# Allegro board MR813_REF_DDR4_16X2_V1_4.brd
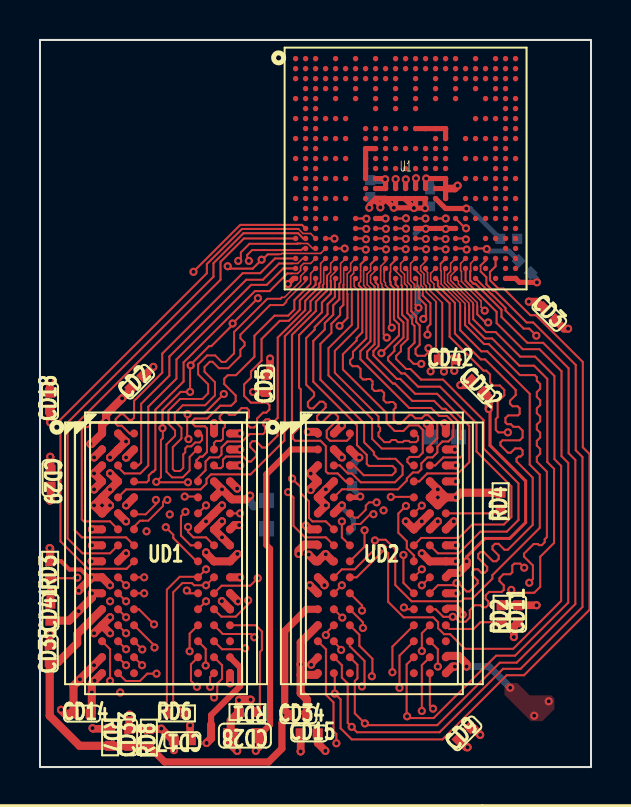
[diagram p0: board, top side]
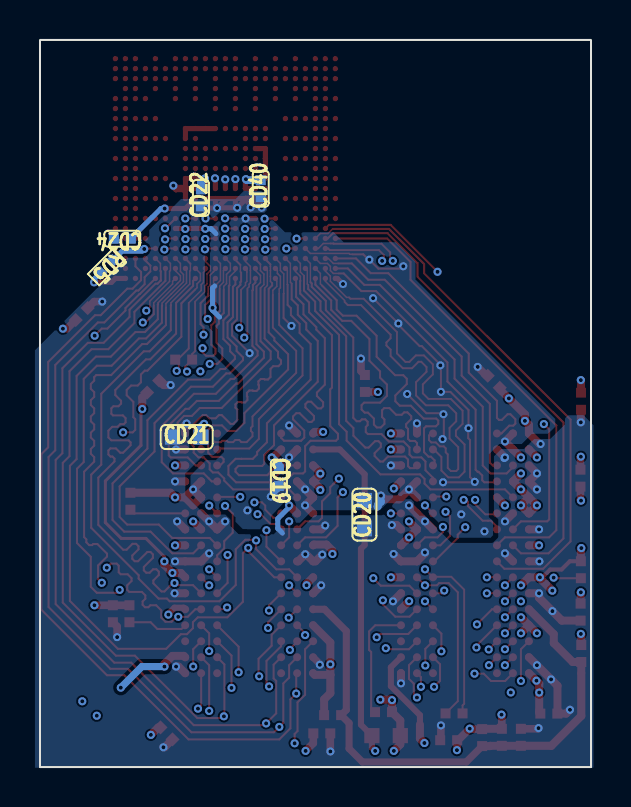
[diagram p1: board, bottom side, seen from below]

Outline 27.56 x 36.39 mm; copper layers: TOP, GND02, POWER03, BOTTOM. Coordinates in mm from the lower left corner of the outline.
Outline path: rectangle 0,0 27.56,36.39

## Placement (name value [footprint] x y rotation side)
CD2  1uF  [C0402]  4.86 19.29 45 top
CD3  1uF  [C0402]  25.47 22.67 315 top
CD5  100nF  [C0402]  11.31 19.2 90 top
CD9  NC/1uF  [C0402]  21.23 1.68 45 top
CD11  100nF  [C0402]  23.91 7.67 90 top
CD12  100nF  [C0402]  21.9 19.04 315 top
CD14  1uF  [C0402]  2.11 2.68 0 top
CD15  1uF  [C0402]  13.46 1.69 0 top
CD17  100nF  [C0402]  7.12 1.34 180 top
CD18  100nF  [C0402]  0.5 18.32 90 top
CD19  1uF  [C0402]  15.61 14.49 270 bottom
CD20  10uF  [C0603]  11.33 12.63 90 bottom
CD21  10uF  [C0603]  20.22 16.52 180 bottom
CD22  1uF  [C0402]  19.51 28.49 90 bottom
CD24  100nF  [C0402]  23.44 26.45 0 bottom
CD28  10uF  [C0603]  10.25 1.57 180 top
CD29  100nF  [C0402]  0.53 14.46 270 top
CD33  100nF  [C0402]  4.46 1.49 90 top
CD34  100nF  [C0402]  12.92 2.6 0 top
CD35  100nF  [C0402]  0.49 5.68 90 top
CD40  NC/1uF  [C0402]  16.52 28.95 90 bottom
CD41  NC/100nF  [C0402]  0.52 7.75 90 top
CD42  NC/2.2nF  [C0402]  20.37 20.39 0 top
NOREF  -  []  -31.22 -1.93 0 top
RD1  240R-1%  [R0402]  10.38 2.75 180 top
RD2  240R-1%  [R0402]  23.09 7.67 90 top
RD3  240R-1%  [R0402]  0.51 9.88 90 top
RD4  240R-1%  [R0402]  23.04 13.3 90 top
RD5  240R-1%  [R0402]  24.24 25.03 315 bottom
RD6  100R  [R0402]  6.85 2.68 0 top
RD7  2K-1%  [R0402]  3.51 1.49 270 top
RD8  2K-1%  [R0402]  5.45 1.47 90 top
U1  MR813  [BGA346P50B1200_1200H114]  18.29 29.96 0 top
UD1  DDR4-FBGA96  [BGA96P80B1000_1400H120]  6.3 10.7 0 top
UD2  DDR4-FBGA96  [BGA96P80B1000_1400H120]  17.1 10.7 0 top

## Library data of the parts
CD2 CD3 CD5 CD9 CD11 CD12 CD14 CD15 CD17-CD22 CD24 CD29 CD33-CD35 CD40-CD42 = C-C0402-X5R
CD28 = C-C0603-X5R
RD1-RD5 RD7 RD8 = R-R0402-1%
RD6 = R-R0402-5%
U1 = A100-BGA
UD1 UD2 = DDR4-FBGA96

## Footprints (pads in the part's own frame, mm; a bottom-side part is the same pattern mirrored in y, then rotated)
BGA96P80B1000_1400H120
  round 0.4 smd: A1(-3.2,6) A2(-2.4,6) A3(-1.6,6) A7(1.6,6) A8(2.4,6) A9(3.2,6) B1(-3.2,5.2) B2(-2.4,5.2) B3(-1.6,5.2) B7(1.6,5.2) B8(2.4,5.2) B9(3.2,5.2) C1(-3.2,4.4) C2(-2.4,4.4) C3(-1.6,4.4) C7(1.6,4.4) C8(2.4,4.4) C9(3.2,4.4) D1(-3.2,3.6) D2(-2.4,3.6) D3(-1.6,3.6) D7(1.6,3.6) D8(2.4,3.6) D9(3.2,3.6) E1(-3.2,2.8) E2(-2.4,2.8) E3(-1.6,2.8) E7(1.6,2.8) E8(2.4,2.8) E9(3.2,2.8) F1(-3.2,2) F2(-2.4,2) F3(-1.6,2) F7(1.6,2) F8(2.4,2) F9(3.2,2) G1(-3.2,1.2) G2(-2.4,1.2) G3(-1.6,1.2) G7(1.6,1.2) G8(2.4,1.2) G9(3.2,1.2) H1(-3.2,0.4) H2(-2.4,0.4) H3(-1.6,0.4) H7(1.6,0.4) H8(2.4,0.4) H9(3.2,0.4) J1(-3.2,-0.4) J2(-2.4,-0.4) J3(-1.6,-0.4) J7(1.6,-0.4) J8(2.4,-0.4) J9(3.2,-0.4) K1(-3.2,-1.2) K2(-2.4,-1.2) K3(-1.6,-1.2) K7(1.6,-1.2) K8(2.4,-1.2) K9(3.2,-1.2) L1(-3.2,-2) L2(-2.4,-2) L3(-1.6,-2) L7(1.6,-2) L8(2.4,-2) L9(3.2,-2) M1(-3.2,-2.8) M2(-2.4,-2.8) M3(-1.6,-2.8) M7(1.6,-2.8) M8(2.4,-2.8) M9(3.2,-2.8) N1(-3.2,-3.6) N2(-2.4,-3.6) N3(-1.6,-3.6) N7(1.6,-3.6) N8(2.4,-3.6) N9(3.2,-3.6) P1(-3.2,-4.4) P2(-2.4,-4.4) P3(-1.6,-4.4) P7(1.6,-4.4) P8(2.4,-4.4) P9(3.2,-4.4) R1(-3.2,-5.2) R2(-2.4,-5.2) R3(-1.6,-5.2) R7(1.6,-5.2) R8(2.4,-5.2) R9(3.2,-5.2) T1(-3.2,-6) T2(-2.4,-6) T3(-1.6,-6) T7(1.6,-6) T8(2.4,-6) T9(3.2,-6)
BGA346P50B1200_1200H114
  round 0.27 smd: A1(-5.5,5.5) A2(-5,5.5) A3(-4.5,5.5) A5(-3.5,5.5) A7(-2.5,5.5) A9(-1.5,5.5) A11(-0.5,5.5) A12(0,5.5) A13(0.5,5.5) A14(1,5.5) A15(1.5,5.5) A16(2,5.5) A17(2.5,5.5) A19(3.5,5.5) A21(4.5,5.5) A22(5,5.5) A23(5.5,5.5) AA1(-5.5,-4.5) AA2(-5,-4.5) AA3(-4.5,-4.5) AA4(-4,-4.5) AA5(-3.5,-4.5) AA6(-3,-4.5) AA7(-2.5,-4.5) AA8(-2,-4.5) AA9(-1.5,-4.5) AA10(-1,-4.5) AA11(-0.5,-4.5) AA12(0,-4.5) AA13(0.5,-4.5) AA14(1,-4.5) AA15(1.5,-4.5) AA16(2,-4.5) AA17(2.5,-4.5) AA18(3,-4.5) AA19(3.5,-4.5) AA20(4,-4.5) AA21(4.5,-4.5) AA22(5,-4.5) AA23(5.5,-4.5) AB1(-5.5,-5) AB2(-5,-5) AB3(-4.5,-5) AB4(-4,-5) AB5(-3.5,-5) AB6(-3,-5) AB7(-2.5,-5) AB8(-2,-5) AB9(-1.5,-5) AB10(-1,-5) AB11(-0.5,-5) AB12(0,-5) AB13(0.5,-5) AB14(1,-5) AB15(1.5,-5) AB16(2,-5) AB17(2.5,-5) AB18(3,-5) AB19(3.5,-5) AB20(4,-5) AB22(5,-5) AB23(5.5,-5) AC1(-5.5,-5.5) AC2(-5,-5.5) AC3(-4.5,-5.5) AC5(-3.5,-5.5) AC7(-2.5,-5.5) AC9(-1.5,-5.5) AC11(-0.5,-5.5) AC13(0.5,-5.5) AC15(1.5,-5.5) AC17(2.5,-5.5) AC19(3.5,-5.5) AC21(4.5,-5.5) AC22(5,-5.5) AC23(5.5,-5.5) B1(-5.5,5) B2(-5,5) B3(-4.5,5) B4(-4,5) B5(-3.5,5) B6(-3,5) B7(-2.5,5) B8(-2,5) B9(-1.5,5) B10(-1,5) B11(-0.5,5) B12(0,5) B13(0.5,5) B14(1,5) B15(1.5,5) B16(2,5) B17(2.5,5) B18(3,5) B19(3.5,5) B20(4,5) B21(4.5,5) B22(5,5) B23(5.5,5) C1(-5.5,4.5) C2(-5,4.5) C3(-4.5,4.5) C4(-4,4.5) C5(-3.5,4.5) C6(-3,4.5) C7(-2.5,4.5) C8(-2,4.5) C9(-1.5,4.5) C10(-1,4.5) C11(-0.5,4.5) C13(0.5,4.5) C15(1.5,4.5) C17(2.5,4.5) C18(3,4.5) C19(3.5,4.5) C20(4,4.5) C21(4.5,4.5) C22(5,4.5) C23(5.5,4.5) D2(-5,4) D3(-4.5,4) D4(-4,4) D5(-3.5,4) D7(-2.5,4) D9(-1.5,4) D11(-0.5,4) D13(0.5,4) D15(1.5,4) D17(2.5,4) D19(3.5,4) D21(4.5,4) D22(5,4) E1(-5.5,3.5) E2(-5,3.5) E3(-4.5,3.5) E5(-3.5,3.5) E7(-2.5,3.5) E9(-1.5,3.5) E11(-0.5,3.5) E13(0.5,3.5) E15(1.5,3.5) E17(2.5,3.5) E20(4,3.5) E21(4.5,3.5) E22(5,3.5) E23(5.5,3.5) F2(-5,3) F3(-4.5,3) F9(-1.5,3) F11(-0.5,3) F13(0.5,3) F22(5,3) F23(5.5,3) G1(-5.5,2.5) G2(-5,2.5) G3(-4.5,2.5) G4(-4,2.5) G5(-3.5,2.5) G6(-3,2.5) G19(3.5,2.5) G20(4,2.5) G21(4.5,2.5) G22(5,2.5) G23(5.5,2.5) H2(-5,2) H3(-4.5,2) H8(-2,2) H9(-1.5,2) H10(-1,2) H11(-0.5,2) H12(0,2) H13(0.5,2) H14(1,2) H15(1.5,2) H16(2,2) H22(5,2) H23(5.5,2) J1(-5.5,1.5) J2(-5,1.5) J3(-4.5,1.5) J4(-4,1.5) J5(-3.5,1.5) J6(-3,1.5) J8(-2,1.5) J9(-1.5,1.5) J10(-1,1.5) J15(1.5,1.5) J16(2,1.5) J18(3,1.5) J19(3.5,1.5) J20(4,1.5) J21(4.5,1.5) J22(5,1.5) J23(5.5,1.5) K2(-5,1) K3(-4.5,1) K8(-2,1) K9(-1.5,1) K10(-1,1) K11(-0.5,1) K12(0,1) K13(0.5,1) K14(1,1) K15(1.5,1) K16(2,1) K21(4.5,1) K22(5,1) L1(-5.5,0.5) L2(-5,0.5) L3(-4.5,0.5) L4(-4,0.5) L5(-3.5,0.5) L6(-3,0.5) L8(-2,0.5) L9(-1.5,0.5) L10(-1,0.5) L14(1,0.5) L15(1.5,0.5) L16(2,0.5) L18(3,0.5) L19(3.5,0.5) L20(4,0.5) L21(4.5,0.5) L22(5,0.5) L23(5.5,0.5) M2(-5,0) M3(-4.5,0) M8(-2,0) M9(-1.5,0) M10(-1,0) M11(-0.5,0) M12(0,0) M13(0.5,0) M14(1,0) M15(1.5,0) M16(2,0) M21(4.5,0) M22(5,0) N1(-5.5,-0.5) N2(-5,-0.5) N3(-4.5,-0.5) N4(-4,-0.5) N5(-3.5,-0.5) N6(-3,-0.5) N8(-2,-0.5) N9(-1.5,-0.5) N15(1.5,-0.5) N16(2,-0.5) N18(3,-0.5) N19(3.5,-0.5) N20(4,-0.5) N21(4.5,-0.5) N22(5,-0.5) N23(5.5,-0.5) P2(-5,-1) P3(-4.5,-1) P8(-2,-1) P9(-1.5,-1) P10(-1,-1) P11(-0.5,-1) P12(0,-1) P13(0.5,-1) P14(1,-1) P15(1.5,-1) P16(2,-1) P21(4.5,-1) P22(5,-1) R1(-5.5,-1.5) R2(-5,-1.5) R3(-4.5,-1.5) R4(-4,-1.5) R5(-3.5,-1.5) R6(-3,-1.5) R8(-2,-1.5) R9(-1.5,-1.5) R10(-1,-1.5) R11(-0.5,-1.5) R12(0,-1.5) R13(0.5,-1.5) R14(1,-1.5) R15(1.5,-1.5) R16(2,-1.5) R18(3,-1.5) R19(3.5,-1.5) R20(4,-1.5) R21(4.5,-1.5) R22(5,-1.5) R23(5.5,-1.5) T2(-5,-2) T3(-4.5,-2) T21(4.5,-2) T22(5,-2) U1(-5.5,-2.5) U2(-5,-2.5) U3(-4.5,-2.5) U4(-4,-2.5) U5(-3.5,-2.5) U7(-2.5,-2.5) U9(-1.5,-2.5) U11(-0.5,-2.5) U13(0.5,-2.5) U15(1.5,-2.5) U17(2.5,-2.5) U18(3,-2.5) U19(3.5,-2.5) U20(4,-2.5) U21(4.5,-2.5) U22(5,-2.5) U23(5.5,-2.5) V2(-5,-3) V3(-4.5,-3) V7(-2.5,-3) V9(-1.5,-3) V11(-0.5,-3) V13(0.5,-3) V15(1.5,-3) V17(2.5,-3) V22(5,-3) V23(5.5,-3) W1(-5.5,-3.5) W2(-5,-3.5) W3(-4.5,-3.5) W4(-4,-3.5) W7(-2.5,-3.5) W9(-1.5,-3.5) W11(-0.5,-3.5) W13(0.5,-3.5) W15(1.5,-3.5) W17(2.5,-3.5) W20(4,-3.5) W21(4.5,-3.5) W22(5,-3.5) W23(5.5,-3.5) Y2(-5,-4) Y3(-4.5,-4) Y4(-4,-4) Y5(-3.5,-4) Y7(-2.5,-4) Y9(-1.5,-4) Y11(-0.5,-4) Y13(0.5,-4) Y15(1.5,-4) Y17(2.5,-4) Y19(3.5,-4) Y22(5,-4) Y23(5.5,-4)
C0402
  rect 0.5x0.5 smd: 1(-0.425,0) 2(0.425,0)
C0603
  rect 0.76x0.76 smd: 1(-0.71,0) 2(0.71,0)
R0402
  rect 0.5x0.5 smd: 1(-0.425,0) 2(0.425,0)

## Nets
GND: CD2.2 CD3.2 CD5.2 CD9.2 CD11.2 CD12.2 CD14.2 CD15.2 CD17.2 CD18.2 CD19.2 CD20.2 CD21.2 CD22.2 CD24.2 CD28.2 CD29.2 CD33.2 CD34.2 CD35.2 CD40.2 CD41.2 RD1.2 RD2.2 RD3.2 RD4.2 RD5.2 RD8.2 U1.A1(GND1) U1.A23(GND2) U1.AA7(GND58) U1.AA11(GND59) U1.AA13(GND60) U1.AA18(GND61) U1.AC1(GND62) U1.AC22(GND63) U1.AC23(GND64) U1.C17(GND3) U1.C19(GND4) U1.H8(GND5) U1.H9(GND6) U1.H10(GND7) U1.H11(GND8) U1.J3(GND9) U1.J8(GND10) U1.J9(GND11) U1.J10(GND12) U1.J15(GND13) U1.J21(GND14) U1.K10(GND15) U1.K11(GND16) U1.K12(GND17) U1.K13(GND18) U1.K14(GND19) U1.K15(GND20) U1.K16(GND21) U1.L9(GND22) U1.L10(GND23) U1.L14(GND24) U1.L15(GND25) U1.L16(GND26) U1.M9(GND27) U1.M10(GND28) U1.M11(GND29) U1.M12(GND30) U1.M13(GND31) U1.M14(GND32) U1.M15(GND33) U1.M16(GND34) U1.N9(GND35) U1.N15(GND36) U1.N16(GND37) U1.N22(GND38) U1.P9(GND39) U1.P10(GND40) U1.P11(GND41) U1.P12(GND42) U1.P13(GND43) U1.P14(GND44) U1.P15(GND45) U1.P16(GND46) U1.R8(GND47) U1.R16(GND48) U1.R21(GND49) U1.U5(GND50) U1.U9(GND51) U1.V2(GND52) U1.V3(GND53) U1.V13(GND54) U1.V15(GND55) U1.V17(GND56) U1.Y4(GND57) UD1.A2(VSSQ1) UD1.A8(VSSQ2) UD1.B2(VSS1) UD1.C9(VSSQ3) UD1.D2(VSSQ4) UD1.D8(VSSQ5) UD1.E1(VSS2) UD1.E3(VSSQ6) UD1.E8(VSSQ7) UD1.E9(VSS3) UD1.F1(VSSQ8) UD1.G8(VSS4) UD1.H1(VSSQ9) UD1.H9(VSSQ10) UD1.K1(VSS5) UD1.K9(VSS6) UD1.M9(VSS7) UD1.N1(VSS8) UD1.T1(VSS9) UD2.A2(VSSQ1) UD2.A8(VSSQ2) UD2.B2(VSS1) UD2.C9(VSSQ3) UD2.D2(VSSQ4) UD2.D8(VSSQ5) UD2.E1(VSS2) UD2.E3(VSSQ6) UD2.E8(VSSQ7) UD2.E9(VSS3) UD2.F1(VSSQ8) UD2.G8(VSS4) UD2.H1(VSSQ9) UD2.H9(VSSQ10) UD2.K1(VSS5) UD2.K9(VSS6) UD2.M9(VSS7) UD2.N1(VSS8) UD2.T1(VSS9)
VCC25-DRAM: CD28.1 CD29.1 UD1.B1(VPP1) UD1.R9(VPP2) UD2.B1(VPP1) UD2.R9(VPP2)
VCC-DRAM: CD2.1 CD3.1 CD5.1 CD9.1 CD11.1 CD12.1 CD14.1 CD15.1 CD17.1 CD18.1 CD19.1 CD20.1 CD21.1 CD22.1 CD40.1 CD41.1 RD7.1 U1.R9(VCC_DRAM1) U1.R10(VCC_DRAM2) U1.R11(VCC_DRAM3) U1.R12(VCC_DRAM4) U1.R13(VCC_DRAM5) U1.R14(VCC_DRAM6) UD1.A1(VDDQ1) UD1.A9(VDDQ2) UD1.B3(VDD1) UD1.B9(VDD2) UD1.C1(VDDQ3) UD1.D1(VDD3) UD1.D9(VDDQ4) UD1.F2(VDDQ5) UD1.F8(VDDQ6) UD1.G1(VDDQ7) UD1.G7(VDD4) UD1.G9(VDDQ8) UD1.J1(VDD5) UD1.J2(VDDQ9) UD1.J8(VDDQ10) UD1.J9(VDD6) UD1.L1(VDD7) UD1.L9(VDD8) UD1.R1(VDD9) UD1.T9(VDD10) UD2.A1(VDDQ1) UD2.A9(VDDQ2) UD2.B3(VDD1) UD2.B9(VDD2) UD2.C1(VDDQ3) UD2.D1(VDD3) UD2.D9(VDDQ4) UD2.F2(VDDQ5) UD2.F8(VDDQ6) UD2.G1(VDDQ7) UD2.G7(VDD4) UD2.G9(VDDQ8) UD2.J1(VDD5) UD2.J2(VDDQ9) UD2.J8(VDDQ10) UD2.J9(VDD6) UD2.L1(VDD7) UD2.L9(VDD8) UD2.R1(VDD9) UD2.T9(VDD10)
VDD18-DRAM: CD24.1 U1.R15(VDD18_DRAM)
VDD-CPU: U1.K8(VDD_CPU1) U1.K9(VDD_CPU2) U1.L8(VDD_CPU3) U1.M8(VDD_CPU4) U1.N8(VDD_CPU5)
VDD-SYS: U1.H13(VDD_SYS1) U1.H14(VDD_SYS2) U1.H15(VDD_SYS3) U1.H16(VDD_SYS4) U1.J16(VDD_SYS5)
SA0: U1.AC19(SA11) UD1.P3(A0) UD2.P3(A0)
SA1: U1.U15(SA3) UD1.P7(A1) UD2.P7(A1)
SA2: U1.AA19(SA9) UD1.R3(A2) UD2.R3(A2)
SA3: U1.Y15(SBA1) UD1.N7(A3) UD2.N7(A3)
SA4: U1.W15(SBA0) UD1.N3(A4) UD2.N3(A4)
SA5: U1.AB16(SA13) UD1.P8(A5) UD2.P8(A5)
SA6: U1.U13(SA4) UD1.P2(A6) UD2.P2(A6)
SA7: U1.W17(SA7) UD1.R8(A7) UD2.R8(A7)
SA8: U1.AA20(SACT) UD1.R2(A8) UD2.R2(A8)
SA9: U1.AB18(SA8) UD1.R7(A9) UD2.R7(A9)
SA10: U1.AB15(SA16) UD1.M3(A10) UD2.M3(A10)
SA11: U1.AA21(SODT0) UD1.T2(A11) UD2.T2(A11)
SA12: U1.AB12(SA15) UD1.M7(A12) UD2.M7(A12)
SA13: U1.Y17(SA12) UD1.T8(A13) UD2.T8(A13)
SACT: U1.AC13(SA14) UD1.L3(ACT) UD2.L3(ACT)
SBA0: U1.W13(SA5) UD1.N2(BA0) UD2.N2(BA0)
SBA1: U1.AA17(SA0) UD1.N8(BA1) UD2.N8(BA1)
SBG0: U1.Y13(SA6) UD1.M2(BG0) UD2.M2(BG0)
SCAS: U1.AC17(SA10) UD1.M8(A15/CAS) UD2.M8(A15/CAS)
SCKE0: U1.AA16(SCKE0) UD1.K2(CKE0) UD2.K2(CKE0)
SCKN: CD42.2 RD6.2 U1.AB14(SCKN) UD1.K8(CK#) UD2.K8(CK#)
SCKP: CD42.1 RD6.1 U1.AA14(SCKP) UD1.K7(CK) UD2.K7(CK)
SCS0: U1.AB13(SA1) UD1.L7(CS0) UD2.L7(CS0)
SDQ0: U1.Y7(SDQ0) UD1.F7(DQ1)
SDQ1: U1.V7(SDQ1) UD1.H8(DQ5)
SDQ2: U1.Y5(SDQ2) UD1.J7(DQ7)
SDQ3: U1.W7(SDQ3) UD1.H7(DQ3)
SDQ4: U1.W1(SDQ4) UD1.H3(DQ2)
SDQ5: U1.W4(SDQ5) UD1.G2(DQ0)
SDQ6: U1.W2(SDQ6) UD1.H2(DQ4)
SDQ7: U1.W3(SDQ7) UD1.J3(DQ6)
SDQ8: U1.AA1(SDQ8) UD1.A3(DQ8)
SDQ9: U1.AB4(SDQ9) UD1.C8(DQ13)
SDQ10: U1.AB1(SDQ10) UD1.C2(DQ12)
SDQ11: U1.AB3(SDQ11) UD1.C7(DQ11)
SDQ12: U1.AC3(SDQ12) UD1.B8(DQ9)
SDQ13: U1.AA4(SDQ13) UD1.D7(DQ15)
SDQ14: U1.AA3(SDQ14) UD1.D3(DQ14)
SDQ15: U1.AA2(SDQ15) UD1.C3(DQ10)
SDQ16: U1.AC9(SDQ16) UD2.D7(DQ15)
SDQ17: U1.AB9(SDQ17) UD2.C8(DQ13)
SDQ18: U1.AA8(SDQ18) UD2.C7(DQ11)
SDQ19: U1.AB8(SDQ19) UD2.B8(DQ9)
SDQ20: U1.AC5(SDQ20) UD2.A3(DQ8)
SDQ21: U1.AB5(SDQ21) UD2.D3(DQ14)
SDQ22: U1.AA6(SDQ22) UD2.C3(DQ10)
SDQ23: U1.AB6(SDQ23) UD2.C2(DQ12)
SDQ24: U1.Y11(SDQ24) UD2.J3(DQ6)
SDQ25: U1.W9(SDQ25) UD2.H2(DQ4)
SDQ26: U1.V9(SDQ26) UD2.H3(DQ2)
SDQ27: U1.Y9(SDQ27) UD2.G2(DQ0)
SDQ28: U1.AC11(SDQ28) UD2.H7(DQ3)
SDQ29: U1.W11(SDQ29) UD2.J7(DQ7)
SDQ30: U1.AB11(SDQ30) UD2.H8(DQ5)
SDQ31: U1.V11(SDQ31) UD2.F7(DQ1)
SDQM0: U1.U7(SDQM0) UD1.E7(DM0)
SDQM1: U1.AA5(SDQM1) UD1.E2(DM1)
SDQM2: U1.AA9(SDQM2) UD2.E2(DM1)
SDQM3: U1.U11(SDQM3) UD2.E7(DM0)
SDQS0N: U1.Y3(SDQS0N) UD1.F3(DQS0#)
SDQS0P: U1.Y2(SDQS0P) UD1.G3(DQS0)
SDQS1N: U1.AC2(SDQS1N) UD1.A7(DQS1#)
SDQS1P: U1.AB2(SDQS1P) UD1.B7(DQS1)
SDQS2N: U1.AC7(SDQS2N) UD2.A7(DQS1#)
SDQS2P: U1.AB7(SDQS2P) UD2.B7(DQS1)
SDQS3N: U1.AA10(SDQS3N) UD2.F3(DQS0#)
SDQS3P: U1.AB10(SDQS3P) UD2.G3(DQS0)
SODT0: U1.AB17(SBG0) UD1.K3(ODT0) UD2.K3(ODT0)
SRAS: U1.AC15(SCS0) UD1.L8(A16/RAS) UD2.L8(A16/RAS)
SRST: U1.U17(SRST) UD1.P1(RESET) UD2.P1(RESET)
STEN1: RD1.1 UD1.N9(TEN)
STEN2: RD2.1 UD2.N9(TEN)
SVREF: CD33.1 CD34.1 CD35.1 RD7.2 RD8.1 UD1.M1(VREFCA) UD2.M1(VREFCA)
SWE: U1.AA12(SA2) UD1.L2(A14/WE) UD2.L2(A14/WE)
N16281101: RD5.1 U1.Y19(SZQ)
N17928021: RD3.1 UD1.F9(ZQ)
N17931224: RD4.1 UD2.F9(ZQ)

Pads without a net: U1 A2 A3 A5 A7 A9 A11 A12 A13 A14 A15 A16 A17 A19 A21 A22 AA15 AA22 AA23 AB19 AB20 AB22 AB23 AC21 B1 B2 B3 B4 B5 B6 B7 B8 B9 B10 B11 B12 B13 B14 B15 B16 B17 B18 B19 B20 B21 B22 B23 C1 C2 C3 C4 C5 C6 C7 C8 C9 C10 C11 C13 C15 C18 C20 C21 C22 C23 D2 D3 D4 D5 D7 D9 D11 D13 D15 D17 D19 D21 D22 E1 E2 E3 E5 E7 E9 E11 E13 E15 E17 E20 E21 E22 E23 F2 F3 F9 F11 F13 F22 F23 G1 G2 G3 G4 G5 G6 G19 G20 G21 G22 G23 H2 H3 H12 H22 H23 J1 J2 J4 J5 J6 J18 J19 J20 J22 J23 K2 K3 K21 K22 L1 L2 L3 L4 L5 L6 L18 L19 L20 L21 L22 L23 M2 M3 M21 M22 N1 N2 N3 N4 N5 N6 N18 N19 N20 N21 N23 P2 P3 P8 P21 P22 R1 R2 R3 R4 R5 R6 R18 R19 R20 R22 R23 T2 T3 T21 T22 U1 U2 U3 U4 U18 U19 U20 U21 U22 U23 V22 V23 W20 W21 W22 W23 Y22 Y23; UD1 P9 T3 T7; UD2 P9 T3 T7

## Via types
v1: diameter 0.406, hole 0.203, TOP to BOTTOM, 273 vias

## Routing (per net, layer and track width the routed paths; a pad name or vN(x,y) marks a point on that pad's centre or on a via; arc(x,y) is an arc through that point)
GND: length 134.8
  TOP w0.076: U1.AA18 21.04,25.21 21.04,24.85 21.08,24.81 21.08,24.31 22.06,23.32 22.06,23.02 v1(22.24,22.84) ; U1.AA13 18.53,25.21 18.53,24.35 18.72,24.17 18.72,24.02 18.77,23.97 18.77,23.14 ; U1.AA7 15.54,25.21 15.54,24.85 15.37,24.68 15.37,23.7 15.38,23.69 ; U1.Y4 14.04,25.71 12.1,25.71 12.06,25.66 11.94,25.66 ; 17.5,24.75 17.54,24.78 17.54,25.14
  TOP w0.102: 11.94,25.66 11.39,25.66 11.12,25.39 v1(11.08,25.39) 10.64,24.95 9.51,24.95 v1(9.39,25.07) ; U1.AA11 17.79,25.39 17.54,25.14 ; U1.V2 13.11,27.14 10.02,27.14 7.68,24.8 v1(7.68,24.79) ; v1(17.08,20.72) 17.08,20.73 17.95,21.6 17.95,22.16 17.7,22.41 17.7,23.97 17.54,24.14 17.54,24.27 17.5,24.31 17.5,24.75 ; 7.4,14.25 5.84,14.25 v1(5.81,14.28) 6.05,14.51 6.05,16.37 6.14,16.46 6.14,16.94 v1(6.13,16.96) 6.13,17.87 7.03,18.78 v1(7.51,18.78) 7.51,20.07 v1(7.54,20.1) 7.54,20.15 8.46,21.07 8.57,21.07 9.63,22.13 v1(9.63,22.2) v1(10.9,23.47) ; 15.38,23.69 15.38,22.48 v1(14.98,22.08) ; v1(7.43,16.41) 7.36,16.48 7.36,17.64 v1(7.38,17.66) 7.43,17.71 8.23,17.71 v1(9.19,18.67) ; 18.77,23.14 v1(18.93,22.98)
  TOP w0.152: v1(21.34,10.3) 21.34,10.52 22.26,11.44 23.49,11.44 24.29,12.24 24.29,14.32 22.51,16.1 22.51,17.86 v1(22.44,17.92)
  TOP w0.203: v1(2.56,9.5) 2.43,9.5 2.04,9.89 1.47,9.89 1.06,10.3 RD3.2
  TOP w0.254: U1.P16 U1.R16 ; U1.P16 U1.P15 ; U1.P16 U1.N16 U1.N15 19.32,29.46 v1(19.31,29.46) 19.29,29.43 U1.P14 ; v1(24.85,24.26) 23.98,24.26 U1.AC23 U1.AC22 ; v1(18.81,29.47) 18.79,29.45 U1.P13 ; U1.P11 17.79,29.43 v1(17.79,29.43) ; U1.V13 19.28,26.96 v1(19.3,26.94) 19.31,26.96 U1.V15 20.27,26.96 v1(20.29,26.93) 20.32,26.96 U1.V17 ; U1.P9 U1.P10 17.29,29.4 v1(17.26,29.42) 17.23,29.46 U1.N9 ; UD2.E3 15.98,13.5 v1(16.02,13.54) ; U1.AC1 12.68,24.46 v1(12.4,24.18) ; U1.U9 v1(17.28,27.46) ; U1.P12 18.29,29.41 v1(18.3,29.42)
  TOP w0.305: v1(21.14,7.63) 21.14,7.67 20.83,7.98 20.38,7.98 UD2.M9
  TOP w0.381: CD15.2 13.89,1.19 v1(14.27,0.81) ; v1(11.51,20.44) 11.51,19.82 CD5.2 ; v1(6.71,0.85) 6.69,0.86 CD17.2 6.64,1.34 v1(6.07,1.92) 6.04,1.9 RD8.2 ; v1(20.89,29.1) 20.74,28.96 U1.P16 ; v1(24.84,8.1) 24.83,8.1 CD11.2 RD2.2 ; CD33.2 4.46,2.61 v1(4.48,2.62) ; v1(26.41,21.94) 26.21,21.94 CD3.2 ; UD1.A2 v1(4.3,16.3) ; v1(0.5,13.33) 0.53,13.36 CD29.2 ; v1(5.67,20.03) 5.23,19.59 CD2.2
  TOP w0.4: v1(14.23,9.1) 14.23,9.17 UD2.K1 ; UD2.G8 v1(19.9,12.3) ; v1(2.7,6.7) UD1.N1 ; UD1.N1 v1(3.5,7.5) ; UD1.N1 v1(3.5,6.7) ; 13.04,4.61 13.04,4.61 13.82,4.61 UD2.T1 ; v1(21.34,10.3) 21.34,10.12 v1(20.94,9.72) 20.52,9.72 UD2.K9 ; v1(0.51,8.75) 0.52,8.74 CD41.2 ; UD2.B2 v1(15.1,15.5) ; CD35.2 0.49,6.64 v1(0.51,6.66) ; v1(2.56,9.5) UD1.K1 v1(3.5,9.1) ; UD2.H1 13.86,11.14 13.23,11.14 12.93,10.84 v1(12.93,10.67) ; v1(19.9,13.9) UD2.E8 19.9,13.1 UD2.E9 ; v1(19.9,13.9) UD2.D8 ; v1(19.9,13.9) UD2.E9 ; CD14.2 2.59,2.73 v1(2.59,3.73) ; CD12.2 22.44,18.5 v1(22.44,17.92) ; UD1.E1 v1(3.5,13.9) UD1.D2 v1(3.5,14.7) ; UD1.E1 v1(3.5,13.1) UD1.F1 v1(2.7,13.1) UD1.E1 ; v1(9.1,13.9) UD1.D8 ; v1(9.1,13.9) UD1.E9 9.6,13.4 10.32,13.4 v1(10.51,13.59) ; v1(9.1,13.9) UD1.E8 ; UD2.A8 19.5,17.03 v1(19.35,17.18) ; v1(10.01,9.5) 10.01,9.5 UD1.K9 ; v1(13.04,5.14) 13.04,6.24 UD2.N1 ; UD1.T1 v1(2.73,4.32) ; UD2.E9 v1(20.8,13.5) ; UD1.H1 v1(2.6,11.1) ; UD1.E3 v1(4.3,13.1) ; v1(10.01,15.1) UD1.C9 ; UD1.M9 v1(9.1,8.3) ; UD2.D2 v1(14.3,13.9) UD2.E1 v1(14.3,13.1) UD2.F1 ; UD2.H9 v1(20.8,11.1) ; UD1.H9 v1(9.1,11.5) UD1.G8 v1(9.1,12.3) ; v1(9.95,3.35) 9.95,3.35 RD1.2 9.54,2.33 CD28.2 9.54,1.13 v1(9.86,0.81) ; CD33.2 5.43,1.91 RD8.2 ; v1(22.01,1.61) 21.64,1.98 CD9.2 ; UD2.C9 v1(20.8,15.1) ; UD2.A2 v1(15.1,17.1) ; UD1.A8 8.7,17.2 v1(8.71,17.2) ; v1(4.3,16.3) UD1.B2 v1(3.5,15.5) ; v1(0.51,19.37) 0.5,19.36 CD18.2 ; CD34.2 13.35,3.39
  TOP w0.406: 13.35,3.39 13.04,3.7 v1(13.04,5.14) ; v1(9.95,3.35) 9.98,3.37 v1(10.54,3.37) ; RD4.2 21.04,13.73 v1(20.8,13.5) ; v1(2.59,3.73) 2.59,4.18 v1(2.73,4.32) ; RD3.2 0.51,10.94 v1(0.48,10.96) ; v1(1.94,8.83) 2.56,9.45 v1(2.56,9.5)
  POWER03 w0.102: v1(11.08,25.39) 10.75,25.72 9.8,25.72 9.53,25.45 9.53,25.21 v1(9.39,25.07)
  BOTTOM w0.254: v1(19.3,26.94) 19,26.94 18.76,26.7 ; RD5.2 24.85,24.42 v1(24.85,24.26) ; 18.82,24.08 18.93,23.97 v1(18.93,22.98) 18.93,22.87 18.58,22.52 ; CD19.2 15.61,13.94 v1(16.02,13.54)
  BOTTOM w0.381: 10.69,13.02 10.66,13.05 10.66,13.12 10.51,13.27 v1(10.51,13.59) ; v1(17.26,29.42) 17.21,29.38 CD40.2 ; v1(19.31,29.46) 19.51,29.26 CD22.2 ; CD21.2 19.51,17.02 v1(19.35,17.18)
  vias: v1(3.5,8.3) v1(4.01,3.73) v1(5.33,11.8) v1(6.49,12.65) v1(7.4,14.25) v1(17.18,12.85) v1(19.54,19.81)
VCC25-DRAM: length 72.1
  TOP w0.305: 8.56,2.13 8.56,2.6 10.01,4.05 10.01,4.99 UD1.R9 ; UD2.B1 12.57,15.9 11.32,14.65 11.32,11.11 11.51,10.93 11.51,2.12 CD28.1 10.96,0.97 v1(10.79,0.81)
  TOP w0.381: v1(0.51,15.53) 0.53,15.51 CD29.1
  TOP w0.4: v1(21.33,5.03) 21.33,5.16 20.93,5.56 20.37,5.56 UD2.R9 ; v1(2.7,15.5) UD1.B1 ; 8.56,1.43 8.56,2.13
  TOP w0.406: v1(8.33,1.2) 8.56,1.43
  POWER03 w0.406: 10.79,0.22 10.79,0.23 v1(10.79,0.81) ; 8.33,0.22 8.33,0.23 v1(8.33,1.2)
  POWER03 w0.508: 1.35,15.5 1.31,15.46 1.31,14.73 ; 1.35,15.5 v1(2.7,15.5) ; 1.35,15.5 0.54,15.5 ; 25.48,3.01 22.69,0.22 3.18,0.22 1.61,1.79 1.61,3.1 1.31,3.4 1.31,14.73 ; 0.54,15.5 1.31,14.73 ; 0.54,15.5 v1(0.51,15.53)
  BOTTOM w0.356: v1(21.33,5.03) 22.46,5.03 v1(23.52,3.97)
  vias: v1(24.72,2.57) v1(25.44,3.29)
VCC-DRAM: length 56.8
  TOP w0.254: U1.R10 17.27,28.47 16.8,28.47 U1.R9 ; U1.R10 17.29,28.4 ; U1.R10 U1.R11 ; U1.R12 U1.R11 ; U1.R12 U1.R13 ; U1.R12 18.29,28.4 18.69,27.99 v1(17.7,27.99) ; U1.R11 17.79,28.08 v1(17.7,27.99) ; U1.R13 18.79,28.06 v1(18.7,27.98) 19.26,27.98 v1(19.26,27.98) 19.26,28.43 U1.R14 U1.R13 ; 17.29,28.4 17.29,28.39 17.02,28.13 17.02,28.09 ; 17.29,28.4 v1(17.7,27.99) ; U1.R9 16.79,28.33 17.02,28.09 ; U1.R9 16.47,28.14 v1(16.47,28) ; 17.02,28.09 v1(17.02,28.01)
  TOP w0.356: v1(13.56,5.12) 13.56,5.16 UD2.R1
  TOP w0.381: v1(24.45,23.3) 24.85,23.3 CD3.1 ; CD5.1 v1(10.66,18.77) ; CD15.1 13.04,0.78 13.03,0.78 v1(13.03,0.78) ; v1(23.7,6.5) 23.7,7.03 CD11.1 ; RD7.1 2.66,1.91 v1(2.63,1.95) ; CD2.1 4.56,18.91 v1(4.11,18.45) ; CD17.1 7.51,1.38 v1(7.51,2.08)
  TOP w0.4: UD2.A9 20.3,17.12 v1(20.22,17.2) ; v1(9.87,10.67) UD1.J9 UD1.J8 8.31,10.69 v1(8.31,10.74) ; UD2.B3 15.9,15.49 v1(15.97,15.49) ; 1.62,2.68 1.24,2.68 v1(1.05,2.87) ; 1.62,2.68 1.68,2.73 1.68,4.07 ; 1.62,2.68 CD14.1 ; v1(9.1,13.1) UD1.F8 v1(8.3,12.3) UD1.G7 ; v1(13.54,13.87) 13.54,13.94 UD2.D1 13.54,14.65 v1(13.54,14.69) 13.54,14.74 UD2.C1 ; v1(20.75,5.03) 20.63,5.03 UD2.T9 ; v1(21.38,0.99) 21.32,0.99 CD9.1 ; CD18.1 0.51,17.88 v1(0.51,17.25) ; UD2.B9 20.75,15.9 v1(20.75,15.9) ; UD2.J2 14.65,10.3 v1(14.29,10.65) 14.25,10.65 UD2.J1 13.78,10.3 v1(13.44,10.63) ; CD12.1 21.37,19.12 v1(21.03,19.12) ; v1(20.8,10.3) UD2.J9 UD2.J8 v1(19.1,10.7) ; UD1.D9 v1(9.86,13.94) ; v1(20.82,8.7) UD2.L9 ; v1(4.3,15.5) UD1.B3 ; UD1.L9 v1(9.9,8.3) ; v1(4.3,10.7) UD1.J2 ; v1(9.96,12.11) 9.72,12.11 UD1.G9 ; UD2.G9 v1(20.7,12.3) ; v1(2.6,8.7) UD1.L1 ; UD2.D9 v1(20.8,14.3) ; 1.47,7.34 1.45,7.33 CD41.1 ; v1(9.5,4.19) UD1.T9 ; UD1.R1 v1(2.7,5.1) ; UD1.J1 v1(2.58,10.3) ; UD1.A9 v1(10.01,16.7) ; v1(18.3,12.3) UD2.G7 v1(19.1,12.3) UD2.F8 ; UD1.G1 v1(2.6,11.9) ; v1(2.7,13.9) UD1.D1 v1(2.7,14.7) UD1.C1 ; v1(13.4,16.78) 13.82,16.78 UD2.A1 ; v1(13.29,12.09) 13.49,11.9 UD2.G1 ; v1(2.52,16.17) 2.58,16.17 UD1.A1 ; v1(10.01,15.9) UD1.B9 ; UD2.F2 v1(15.1,13.1) ; UD1.F2 v1(4.3,12.3) ; UD2.L1 v1(13.5,9.1)
  TOP w0.406: v1(2.6,8.7) 2.6,8.47 v1(1.93,7.8) 1.47,7.34 ; UD1.A1 3.1,17.13 v1(3.3,17.33) 3.3,17.65 4.09,18.44 ; 1.68,4.07 v1(2,4.39) v1(2.7,5.1)
  GND02 w0.254: v1(13.54,14.69) 13.54,14.74 14.73,15.93 15.61,15.93 15.97,15.57 v1(15.97,15.49)
  GND02 w0.305: 15.95,15.49 v1(15.97,15.49)
  BOTTOM w0.254: v1(15.1,13.1) 15.1,13 15.67,12.43 15.67,11.94 15.44,11.71
  BOTTOM w0.381: v1(4.3,15.5) 4.35,15.46 ; v1(15.97,15.49) 15.61,15.14 CD19.1
VDD18-DRAM: length 4.1
  TOP w0.254: U1.R15 20.29,27.96 v1(21.32,27.96)
  BOTTOM w0.254: v1(21.32,27.96) 21.51,27.96 CD24.1
VDD-CPU: length 2
  TOP w0.254: U1.K9 U1.K8 U1.L8 U1.M8 U1.N8
VDD-SYS: length 2
  TOP w0.254: U1.J16 U1.H16 U1.H15 U1.H14 U1.H13
SA0: length 47.1
  TOP w0.102: UD1.P3 v1(5.12,5.89) ; U1.AC19 22.57,23.67 22.59,23.67 23.28,22.97 23.28,22.85 24.19,21.95 24.47,21.95 v1(24.82,21.59) ; UD2.P3 15.5,6.04 16.23,5.31 16.23,4.13 16.13,4.03 v1(16.1,4.03)
  POWER03 w0.102: v1(24.82,21.59) 24.82,21.18 26.36,19.64 26.36,6.67 24.02,4.33 23.37,4.33 22.65,3.61 22.43,3.61 22.07,3.25 19.83,3.25 19.48,3.61 16.53,3.61 v1(16.1,4.03) 14.6,4.03 14.26,3.7 11.72,3.7 11.34,4.08 10.12,4.08 9.47,4.73 6.48,4.73 5.32,5.89 v1(5.12,5.89)
SA1: length 47.9
  TOP w0.102: UD2.P7 17.98,5.58 v1(17.98,3.96) ; v1(8.29,5.08) 8.29,5.91 UD1.P7 ; U1.U15 v1(20.29,27.46)
  POWER03 w0.102: v1(8.29,5.08) 9.62,5.08 10.26,4.44 12.15,4.44 12.54,4.05 14.05,4.05 14.39,4.39 16.25,4.39 16.68,3.96 v1(17.98,3.96) 19.62,3.96 19.98,3.61 21.92,3.61 22.28,3.96 22.5,3.96 23.22,4.68 23.87,4.68 26.01,6.82 26.01,19.49 24.47,21.03 24.47,21.73 23.27,22.93 23.27,23.44 22.74,23.97 22.05,23.97 20.95,25.07 20.95,26.8 v1(20.29,27.46)
SA2: length 50.5
  TOP w0.076: 21.54,24.83 21.54,25.21 U1.AA19
  TOP w0.102: 21.54,24.83 21.52,24.81 21.52,24.36 21.52,24.35 21.52,24.35 21.68,24.19 21.78,24.19 23.08,22.89 23.08,22.53 24.37,21.24 25.16,21.24 26.44,19.96 26.44,15.71 26.78,15.37 26.78,8.16 23.84,5.22 23,5.22 19.87,2.1 16.34,2.1 v1(16.25,2.18) 15.75,2.69 15.75,4.31 15.87,4.44 15.87,5.12 UD2.R3 ; UD1.R3 4.71,5.5 v1(5.1,5.1)
  POWER03 w0.102: v1(16.25,2.18) 15.94,2.18 15.69,2.44 15.51,2.44 14.98,1.9 9.28,1.9 7.16,4.02 5.86,4.02 5.1,4.77 v1(5.1,5.1)
SA3: length 45.9
  TOP w0.102: v1(7.48,5.79) 7.48,6.68 UD1.N7 ; U1.Y15 20.24,25.96 v1(20.29,25.91) ; UD2.N7 17.63,6.02 v1(17.63,4.74)
  POWER03 w0.102: v1(20.29,25.91) 20.29,25.02 20.42,24.89 20.42,24.68 21.84,23.26 22.33,23.26 22.6,22.99 22.6,22.62 23.76,21.46 23.76,20.73 25.3,19.19 25.3,7.11 23.64,5.46 22.99,5.46 22.21,4.67 21.98,4.67 21.63,4.32 20.27,4.32 19.92,4.67 17.7,4.67 v1(17.63,4.74) 16.9,4.74 16.49,5.15 14.1,5.15 13.71,4.76 12.83,4.76 12.45,5.15 10.56,5.15 9.91,5.79 v1(7.48,5.79)
SA4: length 49.3
  TOP w0.102: UD1.N3 5.73,6.07 v1(5.73,5.98) ; U1.W15 20.25,26.46 v1(20.28,26.43) ; v1(16.6,4.54) 16.63,4.57 16.63,5.42 15.97,6.07 15.97,6.62 UD2.N3
  POWER03 w0.102: v1(20.28,26.43) 20.65,26.06 20.65,25.02 20.78,24.89 20.78,24.81 21.97,23.62 22.48,23.62 22.95,23.14 22.95,22.77 24.11,21.61 24.11,20.88 25.65,19.34 25.65,6.97 23.73,5.04 23.08,5.04 22.36,4.32 22.13,4.32 21.77,3.96 20.13,3.96 19.77,4.32 16.82,4.32 v1(16.6,4.54) 16.4,4.74 14.19,4.74 14.07,4.62 13.86,4.41 12.69,4.41 12.3,4.79 10.41,4.79 9.77,5.44 6.87,5.44 6.33,5.98 v1(5.73,5.98)
SA5: length 41.5
  TOP w0.076: U1.AB16 20.23,24.9 20.23,24.23 21.26,23.2 21.26,23
  TOP w0.102: v1(10.26,5.95) 10.21,5.9 9.1,5.9 UD1.P8 ; v1(19.9,5.03) 19.9,5.03 19.9,5.9 UD2.P8 ; 21.26,23 21.26,22.12 22.21,21.17 22.45,21.17 24,19.62 24.75,19.62 24.85,19.52 24.85,19.34 25.02,19.17 25.02,18.93 24.85,18.77 24.85,18.53 25.02,18.36 25.02,18.12 24.85,17.95 24.85,17.71 25.02,17.55 25.02,17.31 24.85,17.14 24.85,16.9 25.02,16.73 25.02,16.5 24.85,16.33 24.85,16.09 25.02,15.92 25.02,15.68 24.85,15.51 24.85,15.29 25.35,14.78 25.35,11.51 25.24,11.39 25.24,11.25 25.1,11.11 24.95,11.11 24.9,11.16 24.69,11.16 24.21,10.68 24.21,10.54 24.65,10.09 24.65,9.41 v1(24.47,9.22)
  POWER03 w0.102: v1(24.47,9.22) 24.47,6.74 23.56,5.83 22.86,5.83 22.06,5.03 21.84,5.03 21.48,4.67 20.42,4.67 20.06,5.03 v1(19.9,5.03) 18.03,5.03 17.93,5.13 17.01,5.13 16.64,5.51 10.7,5.51 v1(10.26,5.95)
SA6: length 45.3
  TOP w0.102: U1.U13 v1(19.28,27.46) ; v1(15.06,5.86) 15.06,5.91 14.7,6.27 UD2.P2 ; v1(4.3,5.9) UD1.P2
  POWER03 w0.102: v1(19.28,27.46) 19.28,27.46 19.92,26.82 19.92,25.04 20.07,24.89 20.07,24.57 21.86,22.78 21.86,22.08 22.97,20.97 22.97,20.29 24.11,19.15 24.11,10.52 23.86,10.27 23.86,9.08 24.11,8.82 24.11,7.4 23.62,6.9 23.43,6.9 21.91,5.39 18.55,5.39 18.45,5.49 17.16,5.49 16.79,5.86 v1(15.06,5.86) 10.85,5.86 10.41,6.3 10.12,6.3 9.96,6.15 7.51,6.15 7.28,6.37 4.78,6.37 v1(4.3,5.9)
SA7: length 49.7
  TOP w0.102: UD2.R8 19.1,5.1 v1(19.1,2.81) ; v1(21.3,26.41) 21.26,26.46 U1.W17 ; v1(8.71,3.48) 8.86,3.64 8.86,4.17 9.1,4.41 9.1,5.1 UD1.R8
  POWER03 w0.102: v1(8.71,3.48) 9.56,2.63 14.7,2.63 15.3,3.23 15.9,3.23 16.23,2.9 19.01,2.9 v1(19.1,2.81) 19.39,2.52 22.34,2.52 22.72,2.9 23.53,2.9 27.08,6.44 27.08,19.96 25.49,21.55 25.49,21.86 25.1,22.25 24.92,22.25 23.95,23.22 23.95,23.91 23.17,24.68 22.32,24.68 21.7,25.31 21.7,26.2 21.49,26.41 v1(21.3,26.41)
SA8: length 51.7
  TOP w0.076: 22.03,25.1 22.03,25.08 22.04,25.08 22.04,24.81
  TOP w0.102: 22.04,24.81 22.33,24.52 22.33,24.17 22.64,23.85 22.74,23.85 24.34,22.25 24.67,22.25 26.79,20.12 26.79,15.85 27.13,15.52 27.13,8.01 24.04,4.92 23.16,4.92 19.98,1.74 15.86,1.74 v1(15.59,2.01) 15.39,2.21 15.39,4.18 15.1,4.47 15.1,5.1 UD2.R2 ; v1(4.3,5.1) UD1.R2 ; 22.03,25.1 22.29,25.35 U1.AA20
  POWER03 w0.102: v1(4.3,5.1) 4.3,4.8 5.44,3.66 7.02,3.66 9.13,1.54 15.12,1.54 v1(15.59,2.01)
SA9: length 46.4
  TOP w0.102: UD1.R7 7.55,5.14 7.55,4.31 v1(7.85,4.02) ; UD2.R7 18.34,5.14 18.34,2.56 v1(18.36,2.54) 18.45,2.45 19.69,2.45 22.81,5.57 23.76,5.57 26.42,8.23 26.42,15.22 26.08,15.56 26.08,19.81 24.98,20.91 24.14,20.91 22.84,22.22 22.84,22.78 21.29,24.33 U1.AB18
  POWER03 w0.102: v1(18.36,2.54) 16.09,2.54 15.75,2.87 15.45,2.87 14.85,2.27 9.41,2.27 7.85,3.83 v1(7.85,4.02)
SA10: length 40.8
  TOP w0.076: 19.79,23.9 19.7,23.99 19.7,24.18 19.54,24.35 19.54,24.71 U1.AB15
  TOP w0.102: UD2.M3 16.15,7.24 v1(16.15,6.96) ; UD1.M3 4.95,7.9 v1(5.7,7.14) ; v1(23.4,16.75) 22.92,16.75 22.8,16.88 22.8,17.42 22.89,17.51 22.89,18.28 23.22,18.61 23.22,18.87 23,19.1 22.67,19.1 22.51,19.26 22.51,19.65 22.32,19.84 22.18,19.84 20.49,21.54 20.49,23.21 19.79,23.9
  POWER03 w0.102: v1(23.4,16.75) 23.4,10.81 23.15,10.56 23.15,9.45 22.79,9.09 22.79,7.77 21.47,6.45 19.56,6.45 19.46,6.55 17.6,6.55 17.2,6.96 v1(16.15,6.96) 12.14,6.96 11.9,7.21 10.01,7.21 9.67,6.86 7.8,6.86 7.52,7.14 v1(5.7,7.14)
SA11: length 50.2
  TOP w0.102: UD2.T2 14.74,4.65 14.74,3.68 v1(14.74,3.68) 15.03,3.39 15.03,1.94 15.59,1.38 20.13,1.38 23.34,4.59 24.21,4.59 27.49,7.87 27.49,15.67 27.15,16 27.15,20.27 24.81,22.62 24.52,22.62 23.19,23.94 22.93,23.94 22.5,24.37 22.5,24.78 22.79,25.06 U1.AA21 ; UD1.T2 4.29,4.31 5,4.31 5.36,4.67 v1(5.83,4.67)
  POWER03 w0.102: v1(14.74,3.68) 14.41,3.34 11.58,3.34 11.19,3.73 9.46,3.73 8.82,4.37 6.15,4.37 6.11,4.4 6.1,4.4 v1(5.83,4.67)
SA12: length 39.6
  TOP w0.076: U1.AB12 18.38,24.86 18.38,24.26 18.57,24.07 18.57,23.95
  TOP w0.102: 18.57,23.95 18.57,22.81 18.82,22.57 18.82,22.28 18.99,22.11 18.99,21.13 18.78,20.93 18.78,20.69 18.88,20.58 19.25,20.58 19.43,20.76 v1(19.43,20.96) ; v1(18.2,7.98) 18.29,7.9 UD2.M7 ; UD1.M7 v1(8.3,8.3)
  POWER03 w0.102: 19.43,20.97 v1(19.43,20.96) 19.69,20.7 20.19,20.7 20.29,20.8 20.29,21.05 20.19,21.15 19.96,21.15 19.86,21.25 19.86,21.45 19.97,21.56 20.44,21.56 21.55,20.46 21.55,19.62 22.29,18.87 22.29,18.66 22.04,18.41 21.72,18.41 21.62,18.31 21.62,17.97 21.77,17.82 22.04,17.82 22.18,17.69 22.18,17.41 22.33,17.25 22.33,11.46 22.23,11.36 21.93,11.36 21.71,11.14 21.71,10.93 22.08,10.56 22.08,9.89 21.68,9.49 21.68,8.17 21.5,7.98 v1(18.2,7.98) 18.18,7.98 17.63,8.54 14.68,8.54 14.52,8.39 12.79,8.39 12.44,8.73 10.29,8.73 10.21,8.65 9.76,8.65 9.53,8.42 9.53,8.23 9.22,7.93 8.67,7.93 v1(8.3,8.3)
SA13: length 46.1
  TOP w0.102: U1.Y17 21.28,25.96 v1(21.34,25.9) ; v1(8.51,4.02) 8.51,4.5 UD1.T8 ; v1(19.66,2.92) 19.5,3.08 UD2.T8
  POWER03 w0.102: v1(21.34,25.9) 21.42,25.82 21.42,25.11 22.2,24.33 23.02,24.33 23.64,23.71 23.64,23.04 24.73,21.95 24.97,21.95 25.18,21.74 25.18,21.33 26.72,19.79 26.72,6.52 23.45,3.25 22.57,3.25 22.22,2.9 19.7,2.9 19.68,2.92 v1(19.66,2.92) 19.49,2.92 19.16,3.25 16.38,3.25 16.05,3.58 15.15,3.58 14.55,2.99 9.7,2.99 8.67,4.02 v1(8.51,4.02)
SACT: length 42.2
  TOP w0.076: U1.AC13 18.88,24.37 18.88,24.08 18.97,23.99 18.97,23.98 18.96,23.97 18.96,23.82 18.95,23.8 18.95,23.51 18.97,23.49 18.97,23.45
  TOP w0.102: v1(16.11,7.83) 16.11,8.09 UD2.L3 ; 18.97,23.45 19.3,23.12 19.3,22.55 v1(19.17,22.43) ; UD1.L3 v1(5.21,8.7)
  POWER03 w0.102: v1(5.21,8.7) 5.98,7.93 7.86,7.93 8.21,7.57 9.37,7.57 9.72,7.92 12.19,7.92 12.44,7.67 14.81,7.67 14.97,7.83 v1(16.11,7.83) 17.33,7.83 17.9,7.27 20.19,7.27 20.29,7.16 21.18,7.16 22.04,8.03 22.04,9.35 22.44,9.75 22.44,10.86 22.69,11.11 22.69,17.05 22.83,17.19 22.83,18.84 21.9,19.76 21.9,20.53 20.57,21.87 20.03,21.87 19.93,21.97 19.93,22.19 20.03,22.3 20.55,22.3 20.65,22.4 20.65,22.59 20.45,22.79 20,22.79 19.9,22.89 19.9,23.37 19.75,23.52 19.46,23.52 19.29,23.34 19.29,22.54 v1(19.17,22.43)
SBA0: length 42.7
  TOP w0.102: v1(14.3,6.61) 14.3,6.7 UD2.N2 ; U1.W13 19.27,26.46 v1(19.3,26.43) ; v1(4.3,6.7) UD1.N2
  POWER03 w0.102: v1(4.3,6.7) 4.37,6.76 7.4,6.76 7.66,6.51 9.81,6.51 10.16,6.85 11.75,6.85 12.02,6.58 14.28,6.58 v1(14.3,6.61) 17.05,6.61 17.46,6.2 19.26,6.2 19.36,6.1 21.62,6.1 23.14,7.62 23.14,8.94 23.51,9.3 23.51,10.42 23.76,10.67 23.76,19 22.62,20.14 22.62,20.83 21.47,21.98 21.47,22.69 19.71,24.44 19.71,24.89 19.67,24.93 19.67,26.06 v1(19.3,26.43)
SBA1: length 40.6
  TOP w0.076: U1.AA17 20.54,25.21 20.54,24.81 20.38,24.66 20.38,24.29 20.99,23.68 20.99,23.68 21.45,23.22 21.45,23.11
  TOP w0.102: 21.45,23.11 21.45,23.1 21.46,23.09 21.46,22.24 22.25,21.45 22.61,21.45 23.97,20.09 24.71,20.09 25.37,19.43 25.37,15.27 25.71,14.93 25.71,11.22 25.02,10.53 25.02,9.02 24.72,8.72 23.72,8.72 v1(23.57,8.87) ; v1(10.72,6.5) 10.56,6.66 9.14,6.66 UD1.N8 ; v1(19.1,5.8) 19.1,6.7 UD2.N8
  POWER03 w0.102: v1(10.72,6.5) 10.99,6.23 16.92,6.23 17.31,5.84 19.06,5.84 v1(19.1,5.8) 19.16,5.74 21.77,5.74 23.23,7.21 23.4,7.21 23.76,7.57 23.76,8.68 v1(23.57,8.87)
SBG0: length 41
  TOP w0.102: v1(19.31,25.92) 19.27,25.96 U1.Y13 ; v1(15.12,7.48) 14.7,7.9 UD2.M2 ; v1(4.3,7.5) UD1.M2
  POWER03 w0.102: v1(19.31,25.92) 19.42,25.81 19.42,24.95 19.39,24.92 19.39,24.32 21.15,22.55 21.15,21.79 22.26,20.68 22.26,19.95 23.25,18.96 23.25,17.1 23.05,16.9 23.05,10.96 22.79,10.71 22.79,9.6 22.39,9.2 22.39,7.88 21.32,6.81 19.74,6.81 19.64,6.91 17.75,6.91 17.2,7.46 15.13,7.46 v1(15.12,7.48) 14.96,7.32 12.29,7.32 12.04,7.56 9.87,7.56 9.52,7.22 7.95,7.22 7.63,7.54 4.34,7.54 v1(4.3,7.5)
SCAS: length 41.2
  TOP w0.076: U1.AC17 20.93,24.32 20.93,24.18 21.87,23.24 21.87,23.1
  TOP w0.102: v1(10.41,8.35) 10.41,8.15 9.79,7.53 9.07,7.53 UD1.M8 ; v1(22.41,22.25) 22.28,22.25 21.87,22.66 21.87,23.1 ; v1(24.22,9.98) 24.01,10.18 23.72,10.18 23.62,10.08 23.62,9.75 23.52,9.65 23.18,9.65 22.98,9.45 22.98,9.31 23.2,9.1 23.2,8.87 23.09,8.77 22.46,8.77 22.29,8.59 22.29,8.42 22.43,8.29 22.43,8.12 22.31,8 22.14,8 22.04,8.1 21.75,8.1 21.5,7.84 21.5,7.48 21.29,7.27 20.98,7.27 20.73,7.52 v1(20.64,7.52) 20.17,7.52 19.79,7.9 UD2.M8
  POWER03 w0.102: v1(10.41,8.35) 12.27,8.35 12.59,8.03 14.66,8.03 14.82,8.19 17.48,8.19 18.04,7.63 20.53,7.63 v1(20.64,7.52) ; v1(24.22,9.98) 24.47,10.23 24.47,11.01 24.92,11.46 24.92,11.61 24.47,12.05 24.47,12.39 24.62,12.54 24.75,12.54 24.9,12.69 24.9,12.9 24.75,13.05 24.62,13.05 24.47,13.2 24.47,13.41 24.62,13.56 24.75,13.56 24.9,13.71 24.9,13.92 24.75,14.06 24.62,14.06 24.47,14.21 24.47,14.42 24.62,14.57 24.75,14.57 24.9,14.72 24.9,14.93 24.75,15.08 24.62,15.08 24.47,15.23 24.47,15.44 24.62,15.59 24.75,15.59 24.9,15.74 24.9,15.95 24.75,16.1 24.62,16.1 24.47,16.25 24.47,16.46 24.62,16.6 24.75,16.6 24.9,16.75 24.9,16.96 24.75,17.11 24.62,17.11 24.47,17.26 24.47,17.47 24.62,17.62 24.75,17.62 24.9,17.77 24.9,17.98 24.75,18.13 24.62,18.13 24.47,18.28 24.47,18.57 24.56,18.67 24.86,18.67 24.93,18.74 24.93,18.95 24.76,19.12 24.57,19.12 24.47,19.22 24.47,19.37 23.34,20.5 23.34,21.33 v1(22.41,22.25)
SCKE0: length 45.7
  TOP w0.076: 20.04,25.19 20.04,24.85 20.07,24.82 20.07,24.18 21.01,23.23 21.01,23.12
  TOP w0.102: v1(4.3,9.1) UD1.K2 ; U1.AA16 20.29,25.44 20.04,25.19 ; UD2.K2 15.1,9.9 15.74,9.9 16.75,10.91 v1(16.75,11.34) 16.78,11.38 17.29,11.38 17.77,10.9 17.77,9.11 18.58,8.3 21.07,8.3 21.21,8.43 21.63,8.43 22.62,9.43 22.62,9.6 25,11.97 25,14.63 24.49,15.14 24.49,18.68 22.37,20.81 22.07,20.81 21.02,21.87 21.02,23.11 21.01,23.12
  POWER03 w0.102: v1(4.3,9.1) 4.3,9.47 5.41,10.57 6.99,10.57 7.08,10.57 8.06,11.54 8.55,11.54 8.87,11.85 9.4,11.85 9.52,11.73 14.86,11.73 15.1,11.5 16.24,11.5 16.39,11.34 v1(16.75,11.34)
SCKN: length 39.2
  TOP w0.076: 20.12,23.23 19.5,23.85 19.5,24.14 19.38,24.26 19.38,24.76 19.29,24.86 U1.AB14
  TOP w0.097: v1(20.72,19.83) 20.62,19.93 20.62,20.21 CD42.2 20.67,20.39 20.12,20.95 20.12,23.23 ; UD1.K8 v1(8.3,9.1) 7.71,9.1 7.6,9.21 7.12,9.21 6.66,8.75 6.66,3.3 RD6.2 ; UD2.K8 v1(19.1,9.1)
  POWER03 w0.097: v1(8.3,9.1) 8.55,9.34 9.18,9.34 9.81,9.96 15.5,9.96 15.67,9.79 18.1,9.79 18.55,9.34 18.86,9.34 v1(19.1,9.1) 19.2,9.2 19.5,9.2 20.44,10.15 20.44,11.24 20.68,11.48 20.83,11.48 21.47,12.12 21.47,16.9 20.52,17.85 20.52,19.61 20.72,19.81 v1(20.72,19.83)
SCKP: length 39.1
  TOP w0.076: 19.8,23.23 19.8,23.3 19.32,23.78 19.32,24.07 19.21,24.18 19.21,24.68 19.04,24.85 19.04,25.06 19.29,25.31 U1.AA14
  TOP w0.097: 19.8,23.23 19.8,20.82 19.95,20.67 CD42.1 20.3,20.04 20.3,19.89 v1(20.21,19.8) ; v1(8.3,9.9) UD1.K7 7.89,9.48 7.77,9.48 7.73,9.52 6.99,9.52 6.34,8.88 6.34,3.17 6.42,3.09 6.42,2.79 6.42,2.69 RD6.1 ; UD2.K7 v1(19.1,9.9)
  POWER03 w0.097: v1(20.21,19.8) 20.21,17.72 21.16,16.76 21.16,12.25 20.7,11.79 20.55,11.79 20.13,11.37 20.13,10.28 19.36,9.52 19.19,9.52 19.1,9.62 v1(19.1,9.9) 18.86,9.66 18.69,9.66 18.23,10.11 15.8,10.11 15.63,10.28 9.68,10.28 9.05,9.66 8.55,9.66 v1(8.3,9.9)
SCS0: length 42
  TOP w0.076: 19.14,23.71 19.14,24.03 19.05,24.12 19.05,24.62 18.88,24.79 18.79,24.89 U1.AB13
  TOP w0.102: UD2.L7 18.18,9.22 v1(18.18,10.62) ; v1(19.38,21.64) 19.38,22.02 19.53,22.17 19.53,23.22 19.14,23.6 19.14,23.71 ; UD1.L7 7.48,8.7 v1(7.34,8.83)
  POWER03 w0.102: v1(7.34,8.83) 7.04,9.14 7.04,9.47 7.85,10.29 8.06,10.29 8.16,10.39 8.46,10.39 8.84,10.78 9.39,10.78 9.63,11.02 14.42,11.02 14.66,10.79 15.86,10.79 16.03,10.61 18.14,10.61 18.16,10.63 ; 18.16,10.63 v1(18.18,10.62) ; 18.16,10.63 18.16,11.73 18.37,11.94 18.9,11.94 19,11.84 19,11.69 18.66,11.36 18.66,11.22 18.83,11.05 19.47,11.05 19.57,11.15 19.57,12 19.45,12.11 19.45,12.55 19.59,12.69 20.3,12.69 20.41,12.8 20.41,15.75 20.31,15.85 20.1,15.85 20.01,15.76 19.54,15.76 19.39,15.9 18.95,15.9 18.78,16.07 18.78,16.69 18.57,16.9 18.36,16.9 18.1,17.15 18.1,17.31 18.4,17.6 19.17,17.6 19.27,17.7 19.27,17.92 19.08,18.11 17.95,18.11 17.82,18.24 17.82,18.5 17.83,18.5 17.94,18.61 19.2,18.61 19.4,18.8 19.4,19.09 19.28,19.21 17.92,19.21 17.82,19.31 17.82,19.44 19.05,20.67 19.05,21.4 19.3,21.64 v1(19.38,21.64)
SDQ0: length 22.1
  TOP w0.102: v1(8.3,13.1) UD1.F7 ; v1(16.29,25.9) 16.24,25.96 U1.Y7
  POWER03 w0.102: v1(8.3,13.1) 8.3,13.6 8.54,13.84 8.54,14.16 8.65,14.26 8.81,14.26 8.91,14.36 8.91,14.74 8.81,14.84 8.57,14.84 8.47,14.94 8.47,15.25 8.57,15.35 8.87,15.35 8.97,15.45 8.97,15.8 8.87,15.9 8.76,15.9 8.66,16 8.66,16.65 9.06,17.05 9.06,17.35 8.66,17.75 8.66,17.92 8.76,18.01 9.07,18.01 9.62,18.56 9.62,19.13 10.33,19.84 11.81,19.84 12.28,20.3 12.28,20.78 12.13,20.93 11.74,20.93 11.63,21.03 11.63,21.33 11.74,21.43 12.12,21.43 12.22,21.53 12.22,21.83 12.47,22.08 12.47,22.29 12.3,22.45 12.3,22.66 12.45,22.81 12.66,22.81 12.83,22.65 13.04,22.65 13.34,22.95 13.34,23.53 13.48,23.67 14.07,23.67 14.33,23.94 14.33,24.57 14.43,24.68 15.07,24.68 v1(16.29,25.9)
SDQ1: length 22.8
  TOP w0.102: v1(16.32,26.93) 16.3,26.96 U1.V7 ; v1(7.41,12.02) 7.41,11.77 7.68,11.5 8.3,11.5 UD1.H8
  POWER03 w0.102: v1(7.41,12.02) 7.41,12.19 7.94,12.73 8.52,12.73 8.75,12.96 8.75,13.33 8.96,13.54 9.25,13.54 9.46,13.75 9.46,14.1 9.33,14.23 9.33,16.89 9.37,16.93 9.37,17.4 9.99,18.02 9.99,18.98 10.46,19.46 11.96,19.46 12.73,20.22 12.73,21.78 16.66,25.71 16.66,26.59 v1(16.32,26.93)
SDQ2: length 22.8
  TOP w0.102: U1.Y5 15.24,25.96 v1(15.24,25.95) ; v1(6.29,12) 6.67,11.63 6.67,11.46 7.83,10.3 UD1.J7
  POWER03 w0.102: v1(15.24,25.95) 14.94,25.65 13.91,25.65 12.97,24.71 11.8,24.71 11.7,24.61 11.7,24.46 11.91,24.26 11.91,24.09 11.46,23.64 11.46,23.38 11.19,23.11 10.67,23.11 10.01,22.45 10.01,21.82 9.28,21.1 9.28,19.9 8.35,18.96 8.22,18.96 7.86,18.61 7.86,16.35 7.76,16.25 7.76,14.11 7.59,13.94 7.59,13.39 7.38,13.18 7.18,13.18 6.88,12.89 6.88,12.11 6.78,12 v1(6.29,12)
SDQ3: length 23.7
  TOP w0.102: v1(7.28,12.78) 7.05,12.55 7.05,11.58 7.54,11.1 UD1.H7 ; v1(16.3,26.42) 16.27,26.46 U1.W7
  POWER03 w0.102: v1(7.28,12.78) 7.45,12.78 7.95,13.28 7.95,13.8 8.11,13.96 8.11,16.1 8.27,16.26 8.27,18.35 9.8,19.88 9.8,20.99 10.07,21.26 10.35,21.26 10.56,21.06 10.56,20.45 10.68,20.33 10.99,20.33 11.13,20.46 11.13,22.32 12.05,23.23 12.44,23.23 12.71,23.5 12.71,23.85 13.03,24.17 13.51,24.17 13.83,24.5 13.83,24.97 14.08,25.22 15.1,25.22 v1(16.3,26.42)
SDQ4: length 24
  TOP w0.102: U1.W1 10.2,26.46 9.03,25.29 9.03,24.39 1.73,17.1 1.73,11.86 2.09,11.5 4.3,11.5 UD1.H3
SDQ5: length 24.5
  TOP w0.102: v1(14.73,26.45) 14.72,26.46 U1.W4 ; v1(2.36,17.17) 2.09,16.9 2.09,12.4 2.19,12.3 3.5,12.3 UD1.G2
  POWER03 w0.102: v1(2.36,17.17) 2.36,17.73 8.91,24.28 8.91,25.23 9.79,26.11 12.41,26.11 12.86,26.57 14.61,26.57 v1(14.73,26.45)
SDQ6: length 25.1
  TOP w0.102: U1.W2 13.17,26.46 12.91,26.72 10.17,26.72 8.68,25.22 8.68,24.54 1.38,17.24 1.38,11.44 2.13,10.7 3.5,10.7 UD1.H2
SDQ7: length 27.7
  TOP w0.076: U1.W3 13.54,26.71 13.15,26.71 12.93,26.93
  TOP w0.102: 12.93,26.93 10.1,26.93 8.35,25.18 8.35,24.71 1.02,17.39 1.02,11.3 2.4,9.92 4.33,9.92 UD1.J3
SDQ8: length 15
  TOP w0.102: U1.AA1 11.75,25.46 11.02,24.72 10.14,24.72 6.11,20.69 6.11,19.74 4.7,18.33 4.7,17.48 4.6,17.37 4.46,17.37 4.18,17.66 4.03,17.66 3.78,17.41 3.78,17.19 3.89,17.09 4.09,17.09 4.48,16.7 UD1.A3
SDQ9: length 14.7
  TOP w0.076: 14.19,24.86 14.19,24.18 14.14,24.13 ; 14.19,24.86 14.19,24.86 ; 14.19,24.86 U1.AB4
  TOP w0.102: 14.14,24.13 14.14,23.93 13.53,23.31 13.53,22.85 12.25,21.56 12.25,17.33 11.88,16.97 11.88,16.59 11.29,15.99 11.12,15.99 10.8,16.31 10.63,16.31 10.51,16.19 10.51,16.02 10.82,15.71 10.82,15.57 10.55,15.29 10.4,15.29 10.15,15.54 9.3,15.54 9.15,15.39 9.15,15.06 9.05,14.96 8.84,14.96 UD1.C8
SDQ10: length 15.6
  TOP w0.102: UD1.C2 3.9,15.01 4.22,14.7 5.02,14.7 5.42,15.09 5.42,18.03 6.83,19.44 6.83,20.4 10.56,24.13 11.34,24.13 12.16,24.96 U1.AB1
SDQ11: length 15.1
  TOP w0.076: 13.45,24.1 13.53,24.18 13.53,24.71 U1.AB3
  TOP w0.102: UD1.C7 7.82,15.18 7.82,15.35 8.01,15.53 8.13,15.53 8.35,15.76 8.35,16.95 8.25,17.06 7.76,17.06 7.64,17.18 7.64,17.34 7.74,17.44 8.37,17.44 9.01,18.09 9.56,18.09 9.79,18.31 9.79,18.6 9.21,19.17 9.21,19.44 9.39,19.61 9.8,19.61 10.72,20.54 10.72,21.59 11.73,22.59 12.41,22.59 12.72,22.9 12.72,23.37 13.45,24.1
SDQ12: length 15.7
  TOP w0.102: UD1.B8 8.7,16.22 8.81,16.32 9.05,16.32 9.15,16.42 9.15,16.92 9.25,17.02 9.25,17.16 8.99,17.42 8.99,17.56 9.18,17.75 9.35,17.75 9.47,17.63 9.75,17.63 10.08,17.96 10.34,17.96 10.45,17.86 10.45,17.52 10.33,17.4 10.33,17.17 10.51,17 10.71,17 10.86,17.14 10.86,17.44 11.16,17.74 11.32,17.74 11.48,17.9 11.48,18.11 11.35,18.24 10.55,18.24 10.21,18.58 10.21,19.15 10.55,19.49 10.55,19.8 11.08,20.33 11.08,21.42 11.99,22.33 12.44,22.33 12.99,22.89 12.99,23.35 13.79,24.14 U1.AC3
SDQ13: length 15.4
  TOP w0.076: U1.AA4 14.03,25.21 14.03,24.27 14.02,24.26
  TOP w0.102: 14.02,24.26 13.97,24.21 13.97,24.04 13.26,23.33 13.26,22.87 11.89,21.5 11.89,17.48 11.72,17.31 11.55,17.31 11.46,17.4 11.29,17.4 11.17,17.28 11.17,17.11 11.26,17.02 11.26,16.77 11.16,16.67 10.48,16.67 10.11,16.29 9.37,16.29 9.08,16 9.08,15.64 8.94,15.5 8.49,15.5 8.28,15.29 8.28,14.86 7.9,14.48 UD1.D7
SDQ14: length 16.3
  TOP w0.076: 12.61,24.71 12.89,24.71 13.03,24.85 13.03,25.06 13.18,25.21 13.53,25.21 U1.AA3
  TOP w0.102: 12.61,24.71 12.37,24.71 11.48,23.82 10.75,23.82 7.18,20.25 7.18,19.3 5.77,17.89 5.77,14.88 5.67,14.78 5.63,14.78 5.44,14.59 5.44,14.35 5.34,14.25 4.75,14.25 UD1.D3
SDQ15: length 15.2
  TOP w0.076: 12.64,25.21 12.89,25.21 13.14,25.46 U1.AA2
  TOP w0.102: 12.64,25.21 11.96,25.21 11.15,24.39 10.31,24.39 6.47,20.55 6.47,19.59 5.06,18.18 5.06,15.24 4.92,15.1 UD1.C3
SDQ16: length 15.3
  TOP w0.102: U1.AC9 16.79,24.25 16.91,24.13 16.91,23.88 16.94,23.85 16.94,21.08 16.67,20.82 16.67,20.6 17.85,19.43 18.02,19.43 18.76,18.68 19.86,18.68 21.47,17.07 21.47,15.26 20.91,14.7 19.37,14.7 19.12,14.45 18.97,14.3 UD2.D7
SDQ17: length 14.3
  TOP w0.076: 16.73,24.05 16.53,24.25 16.53,24.6 16.79,24.86 U1.AB9
  TOP w0.102: UD2.C8 19.77,15.1 20.17,15.5 21.02,15.5 21.12,15.6 21.12,16.35 21.03,16.44 21.03,17.18 20.28,17.93 20.11,17.93 19.71,18.33 18.62,18.33 17.75,19.2 17.65,19.2 16.36,20.49 16.36,20.79 16.73,21.17 16.73,24.05
SDQ18: length 14.5
  TOP w0.076: 16.03,25.16 16.03,25.06 16.03,24.56 16.03,24.31 15.95,24.22
  TOP w0.102: 15.95,24.22 15.95,24.11 16.12,23.93 16.12,21.76 15.84,21.48 15.84,21.35 15.15,20.66 15.15,19.9 17.33,17.71 17.33,17.23 17.74,16.82 18.18,16.82 18.46,17.1 18.93,17.1 19.15,16.88 19.15,15.73 18.94,15.52 18.48,15.52 18.38,15.41 18.38,15.27 18.55,15.1 UD2.C7 ; U1.AA8 16.29,25.41 16.03,25.16
SDQ19: length 14.1
  TOP w0.076: U1.AB8 16.19,24.86 16.19,24.1 16.32,23.96 16.32,23.88
  TOP w0.102: 16.32,23.88 16.32,21.46 15.65,20.78 15.65,20.5 15.5,20.36 15.5,20.19 15.63,20.06 15.89,20.06 16.03,19.93 16.03,19.52 16.15,19.4 16.32,19.4 16.35,19.42 16.52,19.42 16.63,19.3 16.63,19.13 16.61,19.11 16.61,18.94 16.73,18.82 16.9,18.82 16.92,18.85 17.09,18.85 17.21,18.73 17.21,18.56 17.19,18.54 17.19,18.37 17.3,18.25 17.47,18.25 17.5,18.27 17.67,18.27 17.78,18.15 17.78,17.98 17.69,17.89 17.69,17.37 17.89,17.18 18.03,17.18 18.47,17.62 18.61,17.62 18.77,17.46 19.09,17.46 19.25,17.62 19.42,17.62 19.87,17.16 19.87,16.45 19.5,16.08 UD2.B8
SDQ20: length 13.5
  TOP w0.102: U1.AC5 14.75,24.42 14.75,23.53 14.38,23.16 14.38,22.66 13.74,22.02 13.74,21.9 13.31,21.47 13.31,19.14 13.71,18.74 13.71,18.57 13.4,18.26 13.4,18.06 13.5,17.95 13.66,17.95 14,18.29 14.17,18.29 14.28,18.17 14.28,18 13.86,17.57 13.86,17.39 13.98,17.27 14.13,17.27 14.57,17.71 14.74,17.71 14.9,17.55 14.9,17.4 14.34,16.84 14.34,16.49 14.5,16.33 15.35,16.33 15.5,16.48 UD2.A3
SDQ21: length 14
  TOP w0.076: U1.AB5 14.79,24.81 14.54,24.56 14.54,24.34
  TOP w0.102: 14.54,24.34 14.55,24.32 14.55,23.85 14.55,23.84 14.55,23.7 14.1,23.25 14.1,22.76 12.96,21.62 12.96,18.99 13.04,18.91 13.04,17.07 12.66,16.68 12.66,16.43 12.76,16.33 14.03,16.33 14.3,16.06 14.3,14.8 14.4,14.7 14.89,14.7 15.29,14.3 UD2.D3
SDQ22: length 16.3
  TOP w0.076: U1.AA6 15.03,25.21 15.03,24.26 14.97,24.2
  TOP w0.102: 14.97,24.2 14.97,23.41 14.67,23.11 14.67,22.64 14.24,22.22 14.24,21.9 13.67,21.33 13.67,19.29 15.85,17.1 15.85,16.11 16.34,15.62 16.34,15.17 16.45,15.07 17.63,15.07 17.78,14.92 17.78,14.78 17.61,14.61 16.19,14.61 15.7,15.1 UD2.C3
SDQ23: length 17
  TOP w0.076: U1.AB6 15.28,24.96 15.19,24.86 15.19,24.15 15.17,24.14
  TOP w0.102: 15.17,24.14 15.17,23.13 15.01,22.97 15.01,22.62 14.57,22.19 14.57,21.73 14.02,21.18 14.02,19.39 16.21,17.21 16.21,16.26 16.7,15.77 16.7,15.64 16.92,15.43 17.48,15.43 17.78,15.43 18.14,15.07 18.14,14.63 17.75,14.25 16.04,14.25 15.6,14.7 15.4,14.7 15,15.1 UD2.C2
SDQ24: length 19.2
  TOP w0.102: UD2.J3 16.23,11.03 v1(16.23,11.85) ; v1(18.29,25.92) 18.25,25.96 U1.Y11
  POWER03 w0.102: v1(16.23,11.85) 16.44,11.85 16.47,11.88 17.15,11.88 17.84,12.57 17.84,13.26 17.98,13.4 17.98,13.64 17.57,14.05 17.57,15.9 16.56,16.92 16.56,19.69 17.95,21.08 17.95,22.27 17.69,22.53 17.69,23.75 18.29,24.35 v1(18.29,25.92)
SDQ25: length 20.1
  TOP w0.102: v1(17.3,26.42) 17.3,26.42 17.27,26.46 U1.W9 ; UD2.H2 14.3,11.5 13.25,11.5 12.68,12.07 12.68,13.49 v1(12.41,13.76)
  POWER03 w0.102: v1(17.3,26.42) 17.3,26.42 16.95,26.07 16.95,25.37 13.15,21.57 13.15,19.77 11.61,18.23 11.61,14.83 12.41,14.03 v1(12.41,13.76)
SDQ26: length 19
  TOP w0.102: v1(15.1,12.3) 15.1,11.5 UD2.H3 ; v1(17.3,26.94) 17.28,26.96 U1.V9
  POWER03 w0.102: v1(17.3,26.94) 17.68,26.57 17.68,24.99 17.58,24.89 17.58,24.73 16.4,23.55 16.4,22.9 13.94,20.44 13.94,19.46 13.64,19.16 13.64,18.18 14.35,17.47 14.35,16.4 14.37,16.38 14.37,14.78 14.65,14.5 14.65,12.74 v1(15.1,12.3)
SDQ27: length 18.2
  TOP w0.102: UD2.G2 14.3,12.3 13.62,12.3 13.45,12.47 13.45,13.3 13.04,13.71 13.04,14.01 12.88,14.17 12.88,14.17 v1(12.61,14.44) ; v1(17.31,25.91) 17.26,25.96 U1.Y9
  POWER03 w0.102: v1(17.31,25.91) 17.31,25.05 13.56,21.3 13.56,19.66 12.05,18.16 12.05,15 v1(12.61,14.44)
SDQ28: length 21.2
  TOP w0.102: UD2.H7 19.07,11.47 20.95,11.47 21.62,12.14 23.2,12.14 23.58,12.51 23.58,14.05 21.83,15.79 21.83,17.21 20.01,19.04 18.91,19.04 18.25,19.7 18.07,19.7 17.41,20.36 17.41,20.51 17.73,20.83 17.73,21.05 18.18,21.5 18.18,22.25 17.91,22.52 17.91,24.04 17.79,24.16 U1.AC11
SDQ29: length 18.9
  TOP w0.102: v1(18.3,26.44) 18.28,26.46 U1.W11 ; v1(18.3,13.07) 17.92,12.69 17.92,11.73 18.35,11.3 18.35,10.95 18.7,10.6 UD2.J7
  POWER03 w0.102: v1(18.3,26.44) 18.65,26.09 18.65,24.16 18.01,23.52 18.01,22.65 18.25,22.4 18.25,20.95 18.23,20.93 18.23,20.91 16.91,19.6 16.91,18.91 16.91,17.09 17.93,16.07 17.93,14.33 18.42,13.84 18.42,13.19 v1(18.3,13.07)
SDQ30: length 21.7
  TOP w0.076: U1.AB11 17.79,24.83 18.08,24.54 18.08,24.12
  TOP w0.102: UD2.H8 19.9,10.7 20.94,10.7 22.03,11.78 23.35,11.78 23.93,12.37 23.93,14.2 22.19,15.94 22.19,17.36 20.15,19.39 19.06,19.39 18.53,19.92 18.31,19.92 17.81,20.43 17.81,20.57 18.05,20.81 18.05,21.09 18.39,21.42 18.39,22.37 18.11,22.64 18.11,24.08 18.08,24.12
SDQ31: length 18.9
  TOP w0.102: v1(19.1,13.09) 19.09,13.09 UD2.F7 ; v1(18.3,26.95) 18.29,26.96 U1.V11
  POWER03 w0.102: v1(18.3,26.95) 18.95,26.3 18.95,23.96 18.31,23.32 18.31,22.78 18.57,22.52 18.57,20.82 17.27,19.52 17.27,17.16 18.23,16.2 18.23,15.67 18.65,15.25 19.2,15.25 19.31,15.15 19.31,14.73 19.18,14.6 18.59,14.6 18.49,14.5 18.49,14.35 18.64,14.2 19.31,14.2 19.41,14.11 19.41,13.8 19.1,13.48 v1(19.1,13.09)
SDQM0: length 24
  TOP w0.102: U1.U7 16.31,27.46 v1(16.32,27.44) ; v1(7.24,13.54) 7.86,13.54 UD1.E7
  POWER03 w0.102: v1(7.24,13.54) 6.93,13.85 6.93,15.18 7.31,15.57 7.31,15.97 6.89,16.39 6.89,17.12 6.51,17.5 6.51,18.47 7.47,19.43 8.27,19.43 8.47,19.64 8.47,19.78 8.37,19.88 8.22,19.88 8.12,19.98 8.12,20.28 8.22,20.38 8.67,20.38 8.77,20.49 8.77,20.89 8.67,20.99 8.15,20.99 8.05,21.1 8.05,21.48 8.17,21.6 8.89,21.6 9.07,21.78 9.07,22.17 11.29,24.39 11.29,24.96 11.39,25.07 12.82,25.07 13.06,25.3 13.06,25.79 13.36,26.09 14.87,26.09 16.23,27.44 v1(16.32,27.44)
SDQM1: length 19.8
  TOP w0.076: 14.36,24.6 14.54,24.78 14.54,25.21 U1.AA5
  TOP w0.102: 14.36,24.6 14.36,23.85 13.8,23.29 13.8,22.83 12.6,21.63 12.6,17.16 12.22,16.78 12.22,16.34 10.53,14.65 8.55,14.65 8.33,14.42 8.33,14.19 8.03,13.9 4.3,13.9 UD1.E2
SDQM2: length 19.8
  TOP w0.076: 16.53,25.17 16.53,24.85 16.36,24.68 16.36,24.15 16.53,23.98
  TOP w0.102: U1.AA9 16.79,25.42 16.53,25.17 ; UD2.E2 15.1,13.9 15.89,13.9 15.89,13.9 17.9,13.9 18.35,14.34 18.35,14.44 18.65,14.74 18.91,14.74 19.07,14.9 19.07,15.2 19.37,15.5 19.63,15.5 19.87,15.74 19.87,16.04 20.12,16.29 20.42,16.29 20.67,16.54 20.67,17.25 20.35,17.57 19.96,17.57 19.56,17.97 18.47,17.97 16.02,20.42 16.02,20.81 16.53,21.32 16.53,23.98
SDQM3: length 21.3
  TOP w0.102: v1(17.55,13.52) 18.67,13.52 UD2.E7 ; v1(18.3,27.47) 18.29,27.46 U1.U11
  POWER03 w0.102: v1(17.55,13.52) 17.54,13.52 17.54,12.7 17.03,12.19 16.51,12.19 16.45,12.25 16.44,12.25 16.05,12.65 16.05,12.84 15.01,13.88 15.01,14.87 14.72,15.15 14.72,16.46 14.66,16.53 14.66,20.53 16.84,22.72 16.84,23.49 17.93,24.58 17.93,27.1 v1(18.3,27.47)
SDQS0N: length 20.4
  TOP w0.076: U1.Y3 13.64,25.96 13.39,26.21 13.03,26.21
  TOP w0.097: v1(5.8,13.37) 5.83,13.33 5.83,13.2 5.29,12.65 4.77,12.65 4.75,12.65 UD1.F3 ; v1(9.91,25.34) 9.94,25.34 10.05,25.45 10.05,25.76 10.48,26.19 12.86,26.19 12.88,26.21 13.03,26.21
  POWER03 w0.097: v1(5.8,13.37) 5.8,13.6 6.17,13.97 6.17,15.56 5.42,16.31 5.42,19.05 6.68,20.31 6.68,21.41 9.91,24.64 v1(9.91,25.34)
SDQS0P: length 20.2
  TOP w0.097: v1(10.45,25.34) 10.36,25.42 10.36,25.63 10.61,25.87 13.07,25.87 13.15,25.96 U1.Y2 ; v1(6.37,13.37) 6.37,13.37 6.25,13.37 6.15,13.27 6.15,13.06 5.42,12.33 5.14,12.33 5,12.33 4.7,12.03 UD1.G3
  POWER03 w0.097: v1(6.37,13.37) 6.37,13.42 6.29,13.5 6.29,13.64 6.49,13.84 6.49,15.7 5.74,16.44 5.74,18.92 6.99,20.17 6.99,21.27 10.23,24.51 10.23,25.12 v1(10.45,25.34)
